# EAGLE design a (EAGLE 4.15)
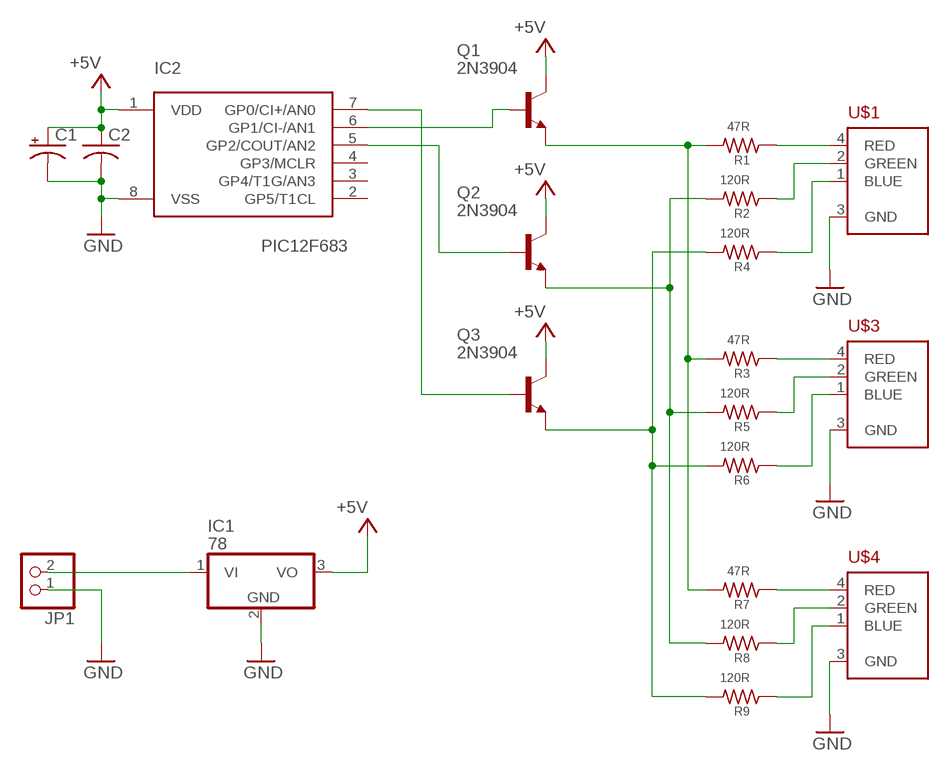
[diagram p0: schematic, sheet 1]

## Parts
C1  CPOL-USE2.5-5  [E2,5-5]
C2  C-US025-024X044  [C025-024X044]
IC1  78  [TO220V]
IC2  PIC12F68329P  [DIL8]
JP1  PINHD-1X2  [1X02]
Q1  2N3904  [TO92]
Q2  2N3904  [TO92]
Q3  2N3904  [TO92]
R1  47R  R-US_0207/10  [0207/10]
R2  120R  R-US_0207/10  [0207/10]
R3  47R  R-US_0207/10  [0207/10]
R4  120R  R-US_0207/10  [0207/10]
R5  120R  R-US_0207/10  [0207/10]
R6  120R  R-US_0207/10  [0207/10]
R7  47R  R-US_0207/10  [0207/10]
R8  120R  R-US_0207/10  [0207/10]
R9  120R  R-US_0207/10  [0207/10]
U$1  5MMRGBLED  [LED5MMRGB]
U$3  5MMRGBLED  [LED5MMRGB]
U$4  5MMRGBLED  [LED5MMRGB]

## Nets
+5V: C1.+ C2.1 IC1.3(VO) IC2.1(VDD) Q1.1(C) Q2.1(C) Q3.1(C)
GND: C1.- C2.2 IC1.2(GND) IC2.8(VSS) JP1.1 U$1.3(GND) U$3.3(GND) U$4.3(GND)
N$1: IC2.6(GP1/CI-/AN1) Q1.2(B)
N$2: R1.1 U$1.4(RED)
N$3: R2.1 U$1.2(GREEN)
N$4: R4.1 U$1.1(BLUE)
N$5: R3.1 U$3.4(RED)
N$6: R5.1 U$3.2(GREEN)
N$7: R6.1 U$3.1(BLUE)
N$8: Q2.3(E) R2.2 R5.2 R8.2
N$9: R7.1 U$4.4(RED)
N$10: R8.1 U$4.2(GREEN)
N$11: R9.1 U$4.1(BLUE)
N$12: Q1.3(E) R1.2 R3.2 R7.2
N$13: IC2.5(GP2/COUT/AN2) Q2.2(B)
N$14: IC2.7(GP0/CI+/AN0) Q3.2(B)
N$15: Q3.3(E) R4.2 R6.2 R9.2
N$16: IC1.1(VI) JP1.2
Unconnected: IC2.2(GP5/T1CL) IC2.3(GP4/T1G/AN3) IC2.4(GP3/MCLR)

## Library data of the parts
C1 = rcl:CPOL-US: POLARIZED CAPACITOR, American symbol
C2 = rcl:C-US: CAPACITOR, American symbol
IC1 = linear:78*: Positive VOLTAGE REGULATOR Source: http://cache.national.com/ds/LM/LM78L05.pdf http://www.fairchildsemi.com/ds/LM/LM7805.pdf
IC2 = microchip PIC12F683:PIC12F683: uPC nW 2k Program Flash memory 2x 8 bitTimer 1x 16 bitTimer Comparator 10b A/D converter/ 4xIN
JP1 = pinhead:PINHD-1X2: PIN HEADER
Q1-Q3 = transistor-npn:2N3904: NPN Transistor
R1-R9 = rcl:R-US_: RESISTOR, American symbol
U$1 U$3 U$4 = led_rgb:5MMRGBLED

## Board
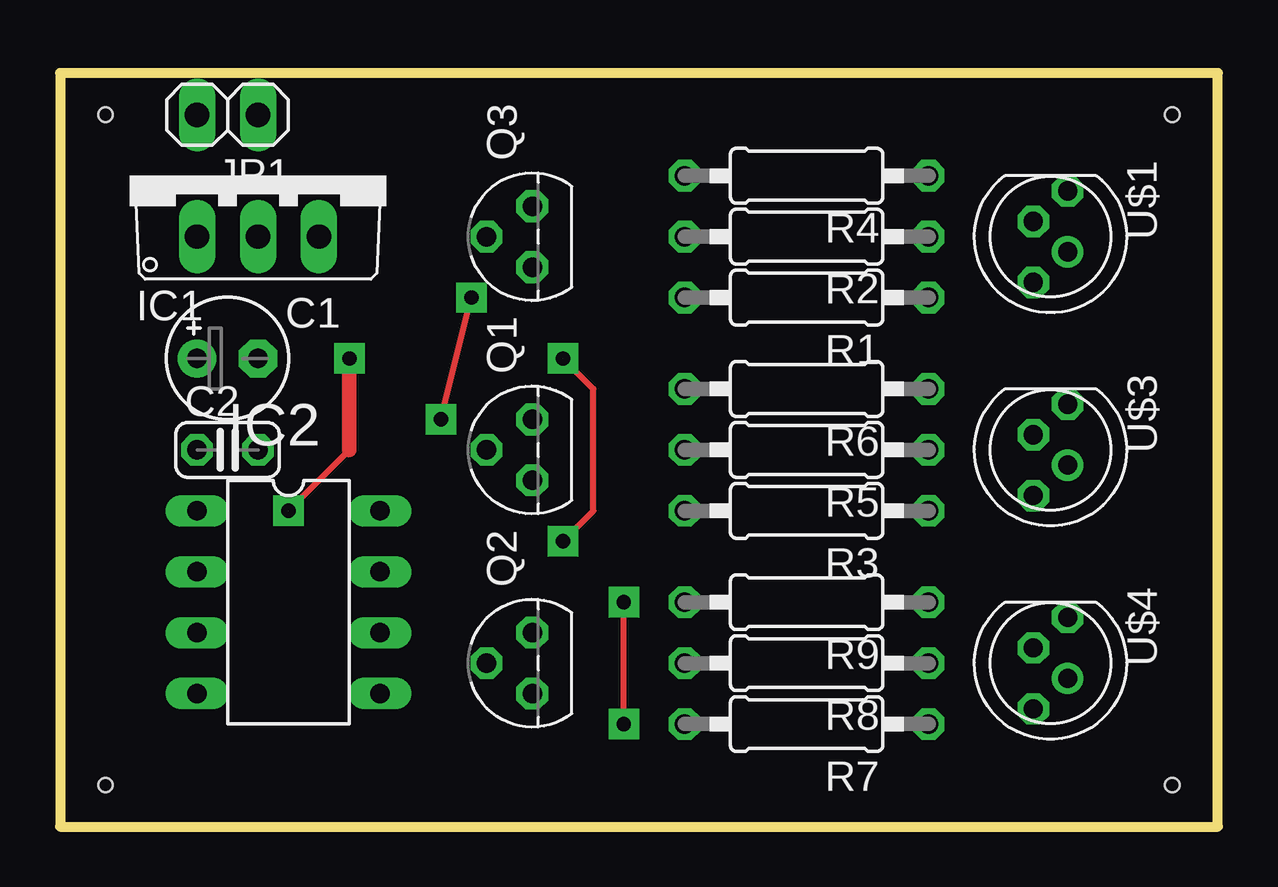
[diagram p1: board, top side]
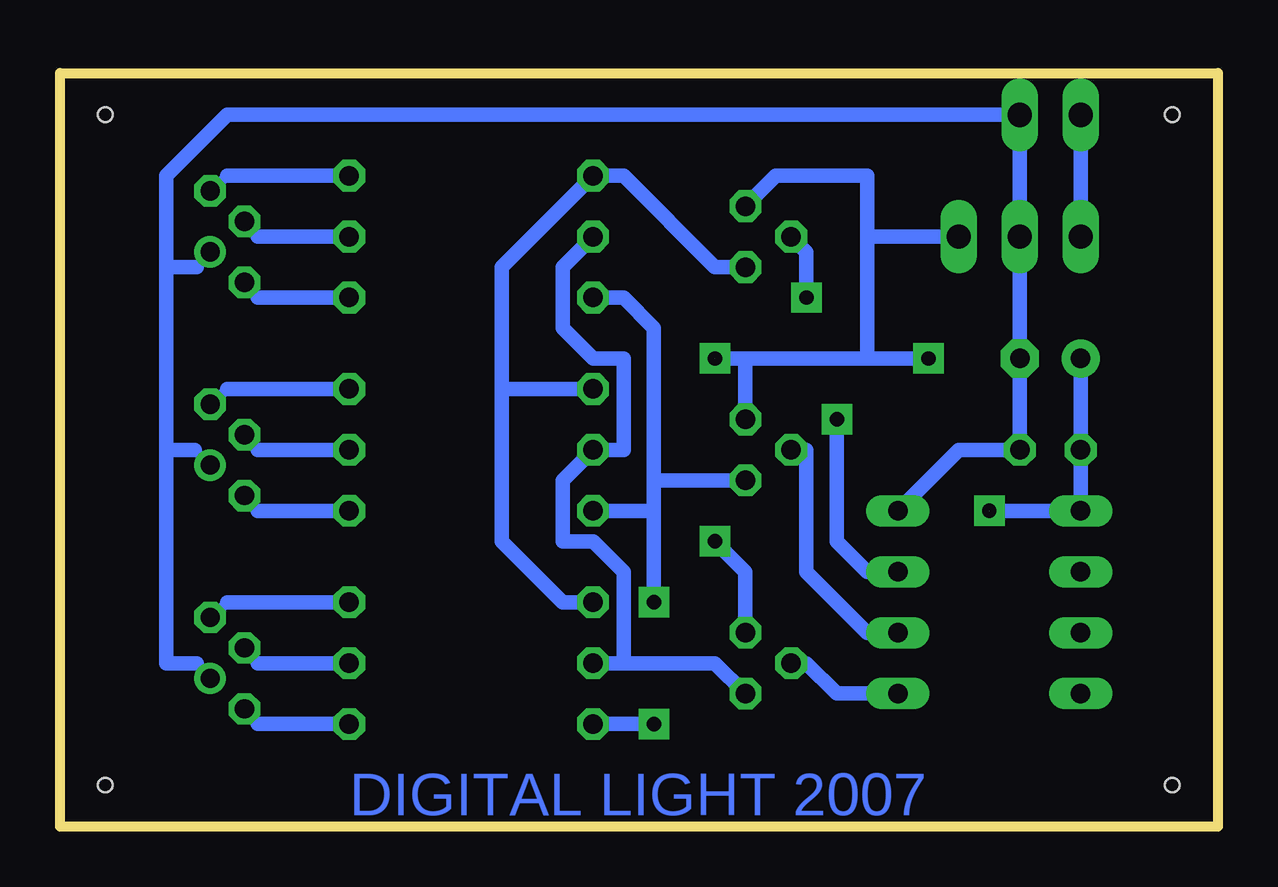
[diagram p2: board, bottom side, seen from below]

Size 48.24 x 31.42 mm. Coordinates in mm from the lower left corner, seen from the top.
Outline: 0,0 48.24,0 48.24,31.42 0,31.42 0,0
Copper layers (1*16): Top 0.035mm / dielectric 1.5mm / Bottom 0.035mm
Design rules "default": minimum track width 10mil, minimum drill 24mil, track to track 8mil, track to pad 8mil, pad to pad 8mil, via to via 8mil, smd to smd 8mil, copper to edge 40mil, drill to drill 8mil, minimum pad ring 10mil, minimum via ring 8mil, stop-mask expansion 4mil, vias tented up to drill 0mil, thermal gap 10mil
Holes 0.6 mm at 1.9,29.68 46.35,1.74 46.35,29.68 1.9,1.74

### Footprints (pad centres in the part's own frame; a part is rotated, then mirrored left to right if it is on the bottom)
E2,5-5 = drill 0.813 pad 1.6 round: + -1.27,0 | drill 0.813 pad 1.6 octagon: - 1.27,0
C025-024X044 = drill 0.813 octagon: 1 -1.27,0; 2 1.27,0
TO220V = drill 1.016 long: 1 -2.54,-2.54; 2 0,-2.54; 3 2.54,-2.54
DIL8 = drill 0.813 long: 1 -3.81,-3.81; 2 -1.27,-3.81; 3 1.27,-3.81; 4 3.81,-3.81; 5 3.81,3.81; 6 1.27,3.81; 7 -1.27,3.81; 8 -3.81,3.81
1X02 = drill 1.016 long: 1 -1.27,0; 2 1.27,0
TO92 = drill 0.813 octagon: 1 1.27,0; 2 0,1.905; 3 -1.27,0
0207/10 = drill 0.813 octagon: 1 -5.08,0; 2 5.08,0
LED5MMRGB = drill 0.8 pad 0.813 octagon: 1 -1.905,0.714; 2 -0.635,-0.714; 4 1.905,-0.714 | drill 0.8 pad 0.813 round: 3 0.635,0.714

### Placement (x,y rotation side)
C1  6.98,19.52 0 top
C2  6.98,15.71 0 top
IC1  8.25,27.14 0 top
IC2  9.52,9.36 270 top
JP1  6.98,29.68 180 top
Q1  19.68,15.71 90 top
Q2  19.68,6.82 90 top
Q3  19.68,24.6 90 top
R1  31.11,22.06 180 top
R2  31.11,24.6 180 top
R3  31.11,13.17 180 top
R4  31.11,27.14 180 top
R5  31.11,15.71 180 top
R6  31.11,18.25 180 top
R7  31.11,4.28 180 top
R8  31.11,6.82 180 top
R9  31.11,9.36 180 top
U$1  41.27,24.6 270 top
U$3  41.27,15.71 270 top
U$4  41.27,6.82 270 top

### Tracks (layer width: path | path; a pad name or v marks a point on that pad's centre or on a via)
+5V  (via drill 0.6 pad 1.27)  (2 unrouted)
  Top 0.254: 9.52,13.17 12.06,15.71 | v20.95,11.9 22.22,13.17 22.22,18.25 20.95,19.52
  Top 0.61: 12.06,15.71 12.06,19.52
  Bottom 0.61: C1.+ C2.1 IC2.1 9.52,13.17 | 14.6,19.52 19.68,19.52 | Q2.1 19.68,10.63 v20.95,11.9 | 19.68,19.52 Q1.1 | 19.68,19.52 20.95,19.52 | 14.6,19.52 12.06,19.52 | Q3.1 18.41,27.14 14.6,27.14 14.6,24.6 | 14.6,24.6 IC1.3 | 14.6,19.52 14.6,24.6
GND
  Bottom 0.254: 43.81,22.06 43.81,15.71 42.54,15.71 U$3.3 | 42.54,6.82 42.54,6.74
  Bottom 0.406: 43.81,22.06 43.81,23.33 | 42.54,23.33 U$1.3 | 42.54,6.74 U$4.3 | 42.62,15.71 U$3.3
  Bottom 0.61: IC2.8 10.79,15.71 C2.2 C1.- IC1.2 JP1.1 41.27,29.68 43.81,27.14 43.81,15.71 | 43.81,15.71 43.81,6.82 42.54,6.82 | 43.81,23.33 42.54,23.33 | 43.81,15.71 42.62,15.71
N$1
  Bottom 0.61: IC2.6 14.6,8.09 17.14,10.63 17.14,15.71 Q1.2
N$2
  Bottom 0.406: 40,22.06 U$1.4
  Bottom 0.61: R1.1 40,22.06
N$3
  Bottom 0.406: 40,24.6 U$1.2
  Bottom 0.61: R2.1 40,24.6
N$4
  Bottom 0.406: 41.27,27.14 U$1.1
  Bottom 0.61: R4.1 41.27,27.14
N$5
  Bottom 0.406: 40,13.17 U$3.4
  Bottom 0.61: R3.1 40,13.17
N$6
  Bottom 0.406: 40,15.71 U$3.2
  Bottom 0.61: R5.1 40,15.71
N$7
  Bottom 0.406: 41.27,18.25 U$3.1
  Bottom 0.61: R6.1 41.27,18.25
N$8
  Bottom 0.61: Q2.3 20.95,6.82 24.76,6.82 | 24.76,6.82 R8.2 | 24.76,6.82 24.76,10.63 26.03,11.9 27.3,11.9 27.3,14.44 R5.2 24.76,15.71 24.76,19.52 26.03,19.52 27.3,20.79 27.3,23.33 R2.2
N$9
  Bottom 0.406: 40,4.28 U$4.4
  Bottom 0.61: R7.1 40,4.28
N$10
  Bottom 0.406: 40,6.82 U$4.2
  Bottom 0.61: R8.1 40,6.82
N$11
  Bottom 0.406: 41.27,9.36 U$4.1
  Bottom 0.61: R9.1 41.27,9.36
N$12  (via drill 0.6 pad 1.27)
  Top 0.254: v23.49,4.28 v23.49,9.36
  Bottom 0.254: 20.95,14.44 22.22,14.44 | 23.49,14.44 23.49,13.17
  Bottom 0.61: Q1.3 20.95,14.44 23.49,14.44 | 23.49,13.17 R3.2 | R1.2 24.76,22.06 23.49,20.79 23.49,14.44 | v23.49,4.28 R7.2 | v23.49,9.36 23.49,14.44
N$13
  Bottom 0.61: IC2.5 15.87,5.55 17.14,6.82 Q2.2
N$14  (via drill 0.6 pad 1.27)
  Top 0.254: v15.87,16.98 v17.14,22.06
  Bottom 0.61: IC2.7 14.6,10.63 15.87,11.9 v15.87,16.98 | Q3.2 17.14,23.96 v17.14,22.06
N$15
  Bottom 0.61: 29.84,18.25 29.84,11.9 27.3,9.36 R9.2 | 29.84,18.25 R6.2 | 29.84,18.25 29.84,23.33 R4.2 24.76,27.14 20.95,23.33 Q3.3
N$16
  Bottom 0.61: IC1.1 JP1.2
N$17  (via drill 0.6 pad 1.27)
  other vias: 20.95,19.52
N$18  (via drill 0.6 pad 1.27)
  other vias: 9.52,13.17
N$19  (via drill 0.6 pad 1.27)
  other vias: 12.06,19.52

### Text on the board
Bottom: DIGITAL LIGHT 2007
